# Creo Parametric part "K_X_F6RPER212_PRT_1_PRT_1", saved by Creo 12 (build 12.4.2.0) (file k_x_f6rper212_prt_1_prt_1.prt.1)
Units: Custom; MM, KILOGRAM, SECS

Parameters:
  PTC_WM_ITERATION = "0"
  PTC_WM_VERSION = "-.0"
  PTC_WM_LIFECYCLE_STATE = "In Work"
  PTC_WM_LIFECYCLE = "MO_CADDocument"
  PTC_WM_CREATED_BY = "Maximilian Roepper (Z0017RMS: MO)"
  PTC_WM_CREATED_ON = "18-Sep-26 11:36:42 AM"
  PTC_WM_MODIFIED_BY = "Maximilian Roepper (Z0017RMS: MO)"
  PTC_WM_MODIFIED_ON = "18-Sep-26 11:36:46 AM"
  PDMLINKNUMBER = "PDM000071454841"
  PTC_WM_NAME = "k_x_f6rper212_prt_1_prt_1.prt"
  PTC_WM_NUMBER = "PDM000071454841"

Other parameters: WEIGHT, WEIGHT_FACTOR, WEIGHT_ADD, _MASS_TEMP, _DIFF_TEMP, MC_ERRORS, SUPPLIER

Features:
  1. coordinate system
  2. datum plane "PRT_YZ"
  3. datum plane "PRT_XY"
  4. datum plane "PRT_XZ"
  5. coordinate system
  6. datum axis
  7. datum axis
  8. datum axis
  9. coordinate system
  10. imported feature
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
Other named items: PRT, SIEMENS_MO, DRW_VIEW_ORG, PRT_X, PRT_Y, PRT_Z, CS0, ROUGH_GROB

Layers: 00_STD_CSYS-KSYS, 01_STD_PLANES-EBENEN, 02_STD_AXES-ACHSEN, 03_STD_CSYS-KSYS, 24_IMPORT_FEAT-IMPORT_KE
